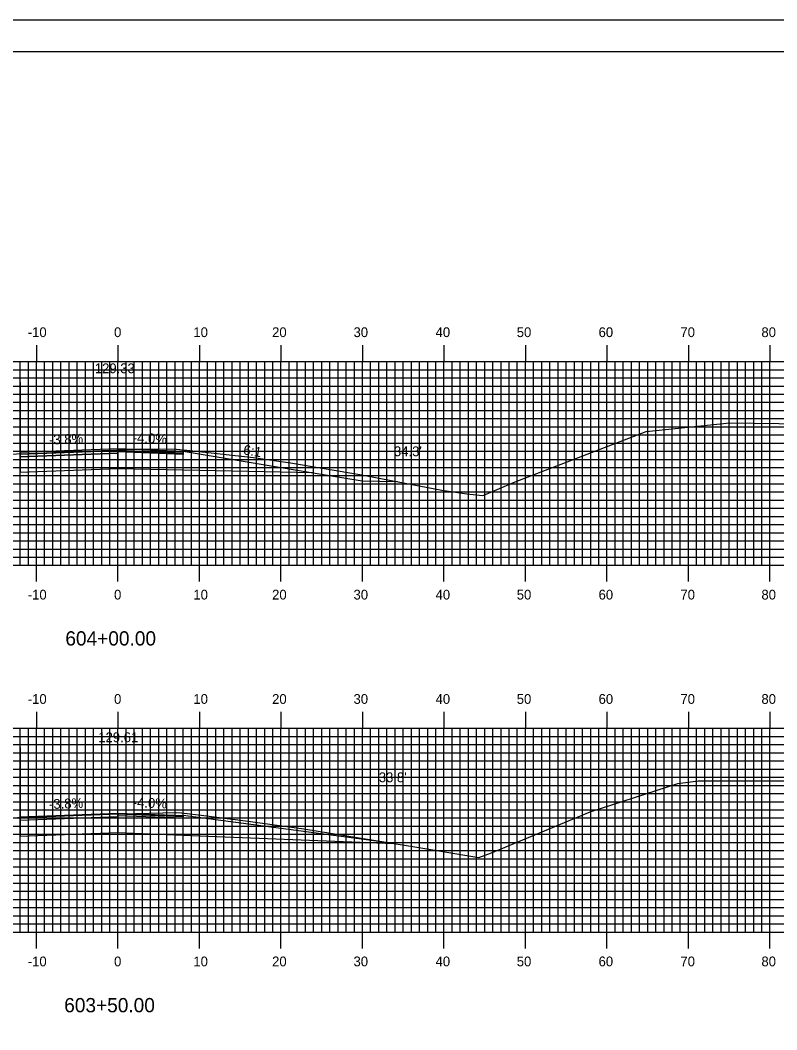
# Model space of a CAD drawing. Extents: x 841782 to 842125, y 363538 to 363758.
# Drawn here: x 841935.4 to 842028.2, y 363633.7 to 363757.6 of the extents above; entities that cross this region are included whole.
import ezdxf

# ---------------------------------------------------------------- set-up
doc = ezdxf.new("R2010")
doc.units = 0
for name, color, linetype in [('ANNOTATION', 7, 'Continuous'), ('BORDER', 7, 'Continuous'), ('D_Roadway_Centerline', 7, 'Continuous'), ('D_Roadway_Centerline_Text', 7, 'Continuous'), ('D_Roadway_Edge_Shoulder', 7, 'Continuous'), ('D_Roadway_Edge_TW', 7, 'Continuous'), ('D_Roadway_FinishedGrade', 7, 'Continuous'), ('D_Roadway_Pavement', 7, 'Continuous'), ('D_Roadway_SubGrade', 7, 'Continuous'), ('D_Text_Standard', 7, 'Continuous'), ('H_V ANNOTATION', 7, 'Continuous'), ('M_Roadway_Centerline', 7, 'Continuous'), ('MAJOR', 7, 'Continuous'), ('MINOR', 7, 'Continuous'), ('PLOT BOUNDARY', 7, 'Continuous'), ('S_Roadway_Centerline', 7, 'Continuous')]:
    doc.layers.add(name, color=color, linetype=linetype)

msp = doc.modelspace()

# ---------------------------------------------------------------- linework, layer by layer
at = {"layer": 'BORDER'}
msp.add_lwpolyline([(841797.77, 363543.72), (842117.77, 363543.72), (842117.77, 363753.72), (841797.77, 363753.72)], close=True, dxfattribs=at)
at = {"layer": 'D_Roadway_Centerline'}
for points in [[(841935.37, 363704.6), (841947.37, 363705.05), (841955.37, 363704.73), (841971.33, 363702.07)], [(841935.37, 363659.87), (841947.37, 363660.33), (841955.37, 363660.01)]]:
    msp.add_lwpolyline(points, dxfattribs=at)
at = {"layer": 'D_Roadway_Edge_Shoulder'}
for points in [[(841947.37, 363705.05), (841955.37, 363704.73), (841955.37, 363704.48), (841947.37, 363704.8)], [(841947.37, 363660.33), (841955.37, 363660.01), (841955.37, 363659.88), (841947.37, 363660.2)]]:
    msp.add_lwpolyline(points, close=True, dxfattribs=at)
at = {"layer": 'D_Roadway_Edge_TW'}
for points in [[(841935.37, 363704.6), (841947.37, 363705.05), (841947.37, 363704.8), (841935.37, 363704.35)], [(841935.37, 363659.87), (841947.37, 363660.33), (841947.37, 363660.2), (841935.37, 363659.75)]]:
    msp.add_lwpolyline(points, close=True, dxfattribs=at)
for points in [[(841935.37, 363704.6), (841935.37, 363704.35)], [(841935.37, 363659.87), (841935.37, 363659.75)]]:
    msp.add_lwpolyline(points, dxfattribs=at)
at = {"layer": 'D_Roadway_FinishedGrade'}
msp.add_lwpolyline([(841971.33, 363702.07), (841977.33, 363701.07), (841981.67, 363700.99)], dxfattribs=at)
at = {"layer": 'D_Roadway_Pavement'}
for points in [[(841935.37, 363704.35), (841947.37, 363704.8), (841947.37, 363704.47), (841935.37, 363704.01)], [(841947.37, 363704.8), (841955.37, 363704.48), (841955.37, 363704.31), (841947.37, 363704.63)]]:
    msp.add_lwpolyline(points, close=True, dxfattribs=at)
for points in [[(841935.37, 363704.35), (841935.37, 363704.01)], [(841947.37, 363704.8), (841947.37, 363704.47)], [(841947.37, 363704.8), (841947.37, 363704.47)]]:
    msp.add_lwpolyline(points, dxfattribs=at)
at = {"layer": 'D_Roadway_SubGrade'}
for p, q in [((841935.37, 363713.19), (841935.37, 363702.1)), ((841935.37, 363668.35), (841935.37, 363659.75)), ((841935.37, 363657.5), (841935.37, 363659.75)), ((841947.37, 363660.2), (841947.37, 363657.95))]:
    msp.add_line(p, q, dxfattribs=at)
for points in [[(841935.37, 363704.01), (841947.37, 363704.47), (841947.37, 363702.55), (841935.37, 363702.1)], [(841947.37, 363704.47), (841947.37, 363704.8), (841955.37, 363704.48), (841955.37, 363704.73), (841971.33, 363702.07), (841947.37, 363702.55)]]:
    msp.add_lwpolyline(points, close=True, dxfattribs=at)
for points in [[(841935.37, 363704.01), (841935.37, 363702.1)], [(841947.37, 363660.2), (841947.37, 363659.87), (841935.37, 363659.42)], [(841935.37, 363659.75), (841935.37, 363657.5), (841947.37, 363657.95), (841955.37, 363657.63), (841955.37, 363659.88)], [(841947.37, 363660.2), (841947.37, 363660.04), (841955.37, 363659.72)], [(841955.37, 363657.63), (841981.21, 363656.6), (841955.37, 363660.01)]]:
    msp.add_lwpolyline(points, dxfattribs=at)
at = {"layer": 'MAJOR'}
for p, q in [((841937.37, 363717.73), (841937.37, 363715.72)), ((841947.37, 363717.73), (841947.37, 363715.72)), ((841957.37, 363717.73), (841957.37, 363715.72)), ((841967.37, 363717.73), (841967.37, 363715.72)), ((841977.37, 363717.73), (841977.37, 363715.72)), ((841987.37, 363717.73), (841987.37, 363715.72)), ((841997.37, 363717.73), (841997.37, 363715.72)), ((842007.37, 363717.73), (842007.37, 363715.72)), ((842017.37, 363717.73), (842017.37, 363715.72)), ((842027.37, 363717.73), (842027.37, 363715.72)), ((841807.37, 363715.72), (842087.37, 363715.72)), ((841807.37, 363715.72), (842087.37, 363715.72)), ((841937.37, 363690.72), (841937.37, 363715.72)), ((841947.37, 363690.72), (841947.37, 363715.72)), ((841957.37, 363690.72), (841957.37, 363715.72)), ((841967.37, 363690.72), (841967.37, 363715.72)), ((841977.37, 363690.72), (841977.37, 363715.72)), ((841987.37, 363690.72), (841987.37, 363715.72)), ((841997.37, 363690.72), (841997.37, 363715.72)), ((842007.37, 363690.72), (842007.37, 363715.72)), ((842017.37, 363690.72), (842017.37, 363715.72)), ((842027.37, 363690.72), (842027.37, 363715.72)), ((841807.37, 363710.72), (842087.37, 363710.72)), ((841807.37, 363705.72), (842087.37, 363705.72)), ((841807.37, 363700.72), (842087.37, 363700.72)), ((841807.37, 363695.72), (842087.37, 363695.72)), ((841807.37, 363690.72), (842087.37, 363690.72)), ((841807.37, 363690.72), (842087.37, 363690.72)), ((841937.37, 363688.72), (841937.37, 363690.72)), ((841947.37, 363688.72), (841947.37, 363690.72)), ((841957.37, 363688.72), (841957.37, 363690.72)), ((841967.37, 363688.72), (841967.37, 363690.72)), ((841977.37, 363688.72), (841977.37, 363690.72)), ((841987.37, 363688.72), (841987.37, 363690.72)), ((841997.37, 363688.72), (841997.37, 363690.72)), ((842007.37, 363688.72), (842007.37, 363690.72)), ((842017.37, 363688.72), (842017.37, 363690.72)), ((842027.37, 363688.72), (842027.37, 363690.72)), ((841937.37, 363672.73), (841937.37, 363670.72)), ((841947.37, 363672.73), (841947.37, 363670.72)), ((841957.37, 363672.73), (841957.37, 363670.72)), ((841967.37, 363672.73), (841967.37, 363670.72)), ((841977.37, 363672.73), (841977.37, 363670.72)), ((841987.37, 363672.73), (841987.37, 363670.72)), ((841997.37, 363672.73), (841997.37, 363670.72)), ((842007.37, 363672.73), (842007.37, 363670.72)), ((842017.37, 363672.73), (842017.37, 363670.72)), ((842027.37, 363672.73), (842027.37, 363670.72)), ((841807.37, 363670.72), (842087.37, 363670.72)), ((841807.37, 363670.72), (842087.37, 363670.72)), ((841937.37, 363645.72), (841937.37, 363670.72)), ((841947.37, 363645.72), (841947.37, 363670.72)), ((841957.37, 363645.72), (841957.37, 363670.72)), ((841967.37, 363645.72), (841967.37, 363670.72)), ((841977.37, 363645.72), (841977.37, 363670.72)), ((841987.37, 363645.72), (841987.37, 363670.72)), ((841997.37, 363645.72), (841997.37, 363670.72)), ((842007.37, 363645.72), (842007.37, 363670.72)), ((842017.37, 363645.72), (842017.37, 363670.72)), ((842027.37, 363645.72), (842027.37, 363670.72)), ((841807.37, 363665.72), (842087.37, 363665.72)), ((841807.37, 363660.72), (842087.37, 363660.72)), ((841807.37, 363655.72), (842087.37, 363655.72)), ((841807.37, 363650.72), (842087.37, 363650.72)), ((841807.37, 363645.72), (842087.37, 363645.72)), ((841807.37, 363645.72), (842087.37, 363645.72)), ((841937.37, 363643.72), (841937.37, 363645.72)), ((841947.37, 363643.72), (841947.37, 363645.72)), ((841957.37, 363643.72), (841957.37, 363645.72)), ((841967.37, 363643.72), (841967.37, 363645.72)), ((841977.37, 363643.72), (841977.37, 363645.72)), ((841987.37, 363643.72), (841987.37, 363645.72)), ((841997.37, 363643.72), (841997.37, 363645.72)), ((842007.37, 363643.72), (842007.37, 363645.72)), ((842017.37, 363643.72), (842017.37, 363645.72)), ((842027.37, 363643.72), (842027.37, 363645.72))]:
    msp.add_line(p, q, dxfattribs=at)
at = {"layer": 'MINOR'}
for p, q in [((841935.37, 363690.72), (841935.37, 363715.72)), ((841936.37, 363690.72), (841936.37, 363715.72)), ((841938.37, 363690.72), (841938.37, 363715.72)), ((841939.37, 363690.72), (841939.37, 363715.72)), ((841940.37, 363690.72), (841940.37, 363715.72)), ((841941.37, 363690.72), (841941.37, 363715.72)), ((841942.37, 363690.72), (841942.37, 363715.72)), ((841943.37, 363690.72), (841943.37, 363715.72)), ((841944.37, 363690.72), (841944.37, 363715.72)), ((841945.37, 363690.72), (841945.37, 363715.72)), ((841946.37, 363690.72), (841946.37, 363715.72)), ((841948.37, 363690.72), (841948.37, 363715.72)), ((841949.37, 363690.72), (841949.37, 363715.72)), ((841950.37, 363690.72), (841950.37, 363715.72)), ((841951.37, 363690.72), (841951.37, 363715.72)), ((841952.37, 363690.72), (841952.37, 363715.72)), ((841953.37, 363690.72), (841953.37, 363715.72)), ((841954.37, 363690.72), (841954.37, 363715.72)), ((841955.37, 363690.72), (841955.37, 363715.72)), ((841956.37, 363690.72), (841956.37, 363715.72)), ((841958.37, 363690.72), (841958.37, 363715.72)), ((841959.37, 363690.72), (841959.37, 363715.72)), ((841960.37, 363690.72), (841960.37, 363715.72)), ((841961.37, 363690.72), (841961.37, 363715.72)), ((841962.37, 363690.72), (841962.37, 363715.72)), ((841963.37, 363690.72), (841963.37, 363715.72)), ((841964.37, 363690.72), (841964.37, 363715.72)), ((841965.37, 363690.72), (841965.37, 363715.72)), ((841966.37, 363690.72), (841966.37, 363715.72)), ((841968.37, 363690.72), (841968.37, 363715.72)), ((841969.37, 363690.72), (841969.37, 363715.72)), ((841970.37, 363690.72), (841970.37, 363715.72)), ((841971.37, 363690.72), (841971.37, 363715.72)), ((841972.37, 363690.72), (841972.37, 363715.72)), ((841973.37, 363690.72), (841973.37, 363715.72)), ((841974.37, 363690.72), (841974.37, 363715.72)), ((841975.37, 363690.72), (841975.37, 363715.72)), ((841976.37, 363690.72), (841976.37, 363715.72)), ((841978.37, 363690.72), (841978.37, 363715.72)), ((841979.37, 363690.72), (841979.37, 363715.72)), ((841980.37, 363690.72), (841980.37, 363715.72)), ((841981.37, 363690.72), (841981.37, 363715.72)), ((841982.37, 363690.72), (841982.37, 363715.72)), ((841983.37, 363690.72), (841983.37, 363715.72)), ((841984.37, 363690.72), (841984.37, 363715.72)), ((841985.37, 363690.72), (841985.37, 363715.72)), ((841986.37, 363690.72), (841986.37, 363715.72)), ((841988.37, 363690.72), (841988.37, 363715.72)), ((841989.37, 363690.72), (841989.37, 363715.72)), ((841990.37, 363690.72), (841990.37, 363715.72)), ((841991.37, 363690.72), (841991.37, 363715.72)), ((841992.37, 363690.72), (841992.37, 363715.72)), ((841993.37, 363690.72), (841993.37, 363715.72)), ((841994.37, 363690.72), (841994.37, 363715.72)), ((841995.37, 363690.72), (841995.37, 363715.72)), ((841996.37, 363690.72), (841996.37, 363715.72)), ((841998.37, 363690.72), (841998.37, 363715.72)), ((841999.37, 363690.72), (841999.37, 363715.72)), ((842000.37, 363690.72), (842000.37, 363715.72)), ((842001.37, 363690.72), (842001.37, 363715.72)), ((842002.37, 363690.72), (842002.37, 363715.72)), ((842003.37, 363690.72), (842003.37, 363715.72)), ((842004.37, 363690.72), (842004.37, 363715.72)), ((842005.37, 363690.72), (842005.37, 363715.72)), ((842006.37, 363690.72), (842006.37, 363715.72)), ((842008.37, 363690.72), (842008.37, 363715.72)), ((842009.37, 363690.72), (842009.37, 363715.72)), ((842010.37, 363690.72), (842010.37, 363715.72)), ((842011.37, 363690.72), (842011.37, 363715.72)), ((842012.37, 363690.72), (842012.37, 363715.72)), ((842013.37, 363690.72), (842013.37, 363715.72)), ((842014.37, 363690.72), (842014.37, 363715.72)), ((842015.37, 363690.72), (842015.37, 363715.72)), ((842016.37, 363690.72), (842016.37, 363715.72)), ((842018.37, 363690.72), (842018.37, 363715.72)), ((842019.37, 363690.72), (842019.37, 363715.72)), ((842020.37, 363690.72), (842020.37, 363715.72)), ((842021.37, 363690.72), (842021.37, 363715.72)), ((842022.37, 363690.72), (842022.37, 363715.72)), ((842023.37, 363690.72), (842023.37, 363715.72)), ((842024.37, 363690.72), (842024.37, 363715.72)), ((842025.37, 363690.72), (842025.37, 363715.72)), ((842026.37, 363690.72), (842026.37, 363715.72)), ((841807.37, 363714.72), (842087.37, 363714.72)), ((841807.37, 363713.72), (842087.37, 363713.72)), ((841807.37, 363712.72), (842087.37, 363712.72)), ((841807.37, 363711.72), (842087.37, 363711.72)), ((841807.37, 363709.72), (842087.37, 363709.72)), ((841807.37, 363708.72), (842087.37, 363708.72)), ((841807.37, 363707.72), (842087.37, 363707.72)), ((841807.37, 363706.72), (842087.37, 363706.72)), ((841807.37, 363704.72), (842087.37, 363704.72)), ((841807.37, 363703.72), (842087.37, 363703.72)), ((841807.37, 363702.72), (842087.37, 363702.72)), ((841807.37, 363701.72), (842087.37, 363701.72)), ((841807.37, 363699.72), (842087.37, 363699.72)), ((841807.37, 363698.72), (842087.37, 363698.72)), ((841807.37, 363697.72), (842087.37, 363697.72)), ((841807.37, 363696.72), (842087.37, 363696.72)), ((841807.37, 363694.72), (842087.37, 363694.72)), ((841807.37, 363693.72), (842087.37, 363693.72)), ((841807.37, 363692.72), (842087.37, 363692.72)), ((841807.37, 363691.72), (842087.37, 363691.72)), ((841807.37, 363669.72), (842087.37, 363669.72)), ((841935.37, 363645.72), (841935.37, 363670.72)), ((841936.37, 363645.72), (841936.37, 363670.72)), ((841938.37, 363645.72), (841938.37, 363670.72)), ((841939.37, 363645.72), (841939.37, 363670.72)), ((841940.37, 363645.72), (841940.37, 363670.72)), ((841941.37, 363645.72), (841941.37, 363670.72)), ((841942.37, 363645.72), (841942.37, 363670.72)), ((841943.37, 363645.72), (841943.37, 363670.72)), ((841944.37, 363645.72), (841944.37, 363670.72)), ((841945.37, 363645.72), (841945.37, 363670.72)), ((841946.37, 363645.72), (841946.37, 363670.72)), ((841948.37, 363645.72), (841948.37, 363670.72)), ((841949.37, 363645.72), (841949.37, 363670.72)), ((841950.37, 363645.72), (841950.37, 363670.72)), ((841951.37, 363645.72), (841951.37, 363670.72)), ((841952.37, 363645.72), (841952.37, 363670.72)), ((841953.37, 363645.72), (841953.37, 363670.72)), ((841954.37, 363645.72), (841954.37, 363670.72)), ((841955.37, 363645.72), (841955.37, 363670.72)), ((841956.37, 363645.72), (841956.37, 363670.72)), ((841958.37, 363645.72), (841958.37, 363670.72)), ((841959.37, 363645.72), (841959.37, 363670.72)), ((841960.37, 363645.72), (841960.37, 363670.72)), ((841961.37, 363645.72), (841961.37, 363670.72)), ((841962.37, 363645.72), (841962.37, 363670.72)), ((841963.37, 363645.72), (841963.37, 363670.72)), ((841964.37, 363645.72), (841964.37, 363670.72)), ((841965.37, 363645.72), (841965.37, 363670.72)), ((841966.37, 363645.72), (841966.37, 363670.72)), ((841968.37, 363645.72), (841968.37, 363670.72)), ((841969.37, 363645.72), (841969.37, 363670.72)), ((841970.37, 363645.72), (841970.37, 363670.72)), ((841971.37, 363645.72), (841971.37, 363670.72)), ((841972.37, 363645.72), (841972.37, 363670.72)), ((841973.37, 363645.72), (841973.37, 363670.72)), ((841974.37, 363645.72), (841974.37, 363670.72)), ((841975.37, 363645.72), (841975.37, 363670.72)), ((841976.37, 363645.72), (841976.37, 363670.72)), ((841978.37, 363645.72), (841978.37, 363670.72)), ((841979.37, 363645.72), (841979.37, 363670.72)), ((841980.37, 363645.72), (841980.37, 363670.72)), ((841981.37, 363645.72), (841981.37, 363670.72)), ((841982.37, 363645.72), (841982.37, 363670.72)), ((841983.37, 363645.72), (841983.37, 363670.72)), ((841984.37, 363645.72), (841984.37, 363670.72)), ((841985.37, 363645.72), (841985.37, 363670.72)), ((841986.37, 363645.72), (841986.37, 363670.72)), ((841988.37, 363645.72), (841988.37, 363670.72)), ((841989.37, 363645.72), (841989.37, 363670.72)), ((841990.37, 363645.72), (841990.37, 363670.72)), ((841991.37, 363645.72), (841991.37, 363670.72)), ((841992.37, 363645.72), (841992.37, 363670.72)), ((841993.37, 363645.72), (841993.37, 363670.72)), ((841994.37, 363645.72), (841994.37, 363670.72)), ((841995.37, 363645.72), (841995.37, 363670.72)), ((841996.37, 363645.72), (841996.37, 363670.72)), ((841998.37, 363645.72), (841998.37, 363670.72)), ((841999.37, 363645.72), (841999.37, 363670.72)), ((842000.37, 363645.72), (842000.37, 363670.72)), ((842001.37, 363645.72), (842001.37, 363670.72)), ((842002.37, 363645.72), (842002.37, 363670.72)), ((842003.37, 363645.72), (842003.37, 363670.72)), ((842004.37, 363645.72), (842004.37, 363670.72)), ((842005.37, 363645.72), (842005.37, 363670.72)), ((842006.37, 363645.72), (842006.37, 363670.72)), ((842008.37, 363645.72), (842008.37, 363670.72)), ((842009.37, 363645.72), (842009.37, 363670.72)), ((842010.37, 363645.72), (842010.37, 363670.72)), ((842011.37, 363645.72), (842011.37, 363670.72)), ((842012.37, 363645.72), (842012.37, 363670.72)), ((842013.37, 363645.72), (842013.37, 363670.72)), ((842014.37, 363645.72), (842014.37, 363670.72)), ((842015.37, 363645.72), (842015.37, 363670.72)), ((842016.37, 363645.72), (842016.37, 363670.72)), ((842018.37, 363645.72), (842018.37, 363670.72)), ((842019.37, 363645.72), (842019.37, 363670.72)), ((842020.37, 363645.72), (842020.37, 363670.72)), ((842021.37, 363645.72), (842021.37, 363670.72)), ((842022.37, 363645.72), (842022.37, 363670.72)), ((842023.37, 363645.72), (842023.37, 363670.72)), ((842024.37, 363645.72), (842024.37, 363670.72)), ((842025.37, 363645.72), (842025.37, 363670.72)), ((842026.37, 363645.72), (842026.37, 363670.72)), ((841807.37, 363668.72), (842087.37, 363668.72)), ((841807.37, 363667.72), (842087.37, 363667.72)), ((841807.37, 363666.72), (842087.37, 363666.72)), ((841807.37, 363664.72), (842087.37, 363664.72)), ((841807.37, 363663.72), (842087.37, 363663.72)), ((841807.37, 363662.72), (842087.37, 363662.72)), ((841807.37, 363661.72), (842087.37, 363661.72)), ((841807.37, 363659.72), (842087.37, 363659.72)), ((841807.37, 363658.72), (842087.37, 363658.72)), ((841807.37, 363657.72), (842087.37, 363657.72)), ((841807.37, 363656.72), (842087.37, 363656.72)), ((841807.37, 363654.72), (842087.37, 363654.72)), ((841807.37, 363653.72), (842087.37, 363653.72)), ((841807.37, 363652.72), (842087.37, 363652.72)), ((841807.37, 363651.72), (842087.37, 363651.72)), ((841807.37, 363649.72), (842087.37, 363649.72)), ((841807.37, 363648.72), (842087.37, 363648.72)), ((841807.37, 363647.72), (842087.37, 363647.72)), ((841807.37, 363646.72), (842087.37, 363646.72))]:
    msp.add_line(p, q, dxfattribs=at)
at = {"layer": 'PLOT BOUNDARY'}
msp.add_lwpolyline([(841781.59, 363537.6), (842121.59, 363537.6), (842121.59, 363757.6), (841781.59, 363757.6)], close=True, dxfattribs=at)
at = {"layer": 'S_Roadway_Centerline'}
for points in [[(841930.58, 363704.09), (841935.44, 363704.42), (841935.57, 363704.41), (841945.33, 363704.81), (841949.46, 363704.97), (841951.34, 363705.01), (841954.54, 363704.97), (841955.81, 363704.84), (841963.98, 363703.95), (841968.53, 363703.29), (841977.03, 363701.88), (841987.09, 363699.94), (841990.19, 363699.47), (841992.08, 363699.29), (841992.24, 363699.32), (841996.12, 363700.96), (842012.16, 363707.12), (842022.46, 363708.19), (842031.49, 363708.07)], [(841931.97, 363659.56), (841935.64, 363659.83), (841935.92, 363659.82), (841943.55, 363660.13), (841943.82, 363660.14), (841944.45, 363660.16), (841954.54, 363660.38), (841955.16, 363660.37), (841957.9, 363660.02), (841963, 363659.36), (841970.17, 363658.4), (841981.73, 363656.52), (841983.55, 363656.22), (841991.66, 363654.88), (841993.22, 363655.46), (841997.54, 363657.25), (842005.3, 363660.49), (842016.08, 363663.96), (842018.57, 363664.29), (842031.62, 363664.29)]]:
    msp.add_lwpolyline(points, dxfattribs=at)

# ---------------------------------------------------------------- texts
at = {"layer": 'ANNOTATION'}
for s, rotation, p in [('-3.8%', 2.1762, (841938.93, 363705.53)), ('-4.0%', 357.7094, (841949.16, 363705.78)), ('6:1', 350.5375, (841962.68, 363704.34)), ('-3.8%', 2.1762, (841938.93, 363660.81)), ('-4.0%', 357.7094, (841949.16, 363661.06))]:
    msp.add_text(s, height=1.2, rotation=rotation, dxfattribs=at).set_placement(p)
at = {"layer": 'D_Roadway_Centerline_Text'}
for s, p in [('129.33', (841944.53, 363714.29)), ('129.61', (841944.95, 363669.02))]:
    msp.add_text(s, height=1.2, dxfattribs=at).set_placement(p)
at = {"layer": 'D_Text_Standard'}
for s, p in [("34.3'", (841981.23, 363704.11)), ("33.8'", (841979.37, 363664.11))]:
    msp.add_text(s, height=1.2, dxfattribs=at).set_placement(p)
at = {"layer": 'H_V ANNOTATION'}
for s, height, p in [('-10', 1.2, (841936.3, 363718.72)), ('0', 1.2, (841946.89, 363718.72)), ('10', 1.2, (841956.62, 363718.72)), ('20', 1.2, (841966.28, 363718.72)), ('30', 1.2, (841976.27, 363718.72)), ('40', 1.2, (841986.34, 363718.72)), ('50', 1.2, (841996.3, 363718.72)), ('60', 1.2, (842006.34, 363718.72)), ('70', 1.2, (842016.38, 363718.72)), ('80', 1.2, (842026.32, 363718.72)), ('-10', 1.2, (841936.3, 363686.52)), ('0', 1.2, (841946.89, 363686.52)), ('10', 1.2, (841956.62, 363686.52)), ('20', 1.2, (841966.28, 363686.52)), ('30', 1.2, (841976.27, 363686.52)), ('40', 1.2, (841986.34, 363686.52)), ('50', 1.2, (841996.3, 363686.52)), ('60', 1.2, (842006.34, 363686.52)), ('70', 1.2, (842016.38, 363686.52)), ('80', 1.2, (842026.32, 363686.52)), ('604+00.00', 1.75, (841940.91, 363680.88)), ('-10', 1.2, (841936.3, 363673.72)), ('0', 1.2, (841946.89, 363673.72)), ('10', 1.2, (841956.62, 363673.72)), ('20', 1.2, (841966.28, 363673.72)), ('30', 1.2, (841976.27, 363673.72)), ('40', 1.2, (841986.34, 363673.72)), ('50', 1.2, (841996.3, 363673.72)), ('60', 1.2, (842006.34, 363673.72)), ('70', 1.2, (842016.38, 363673.72)), ('80', 1.2, (842026.32, 363673.72)), ('-10', 1.2, (841936.3, 363641.52)), ('0', 1.2, (841946.89, 363641.52)), ('10', 1.2, (841956.62, 363641.52)), ('20', 1.2, (841966.28, 363641.52)), ('30', 1.2, (841976.27, 363641.52)), ('40', 1.2, (841986.34, 363641.52)), ('50', 1.2, (841996.3, 363641.52)), ('60', 1.2, (842006.34, 363641.52)), ('70', 1.2, (842016.38, 363641.52)), ('80', 1.2, (842026.32, 363641.52)), ('603+50.00', 1.75, (841940.77, 363635.88))]:
    msp.add_text(s, height=height, dxfattribs=at).set_placement(p)
at = {"layer": 'M_Roadway_Centerline'}
for s, p in [('C', (841935.43, 363704.42)), ('L', (841935.44, 363704.41)), ('C', (841935.63, 363659.83)), ('L', (841935.64, 363659.82))]:
    msp.add_text(s, height=0.0146, dxfattribs=at).set_placement(p)

doc.saveas('drawing.dxf')
